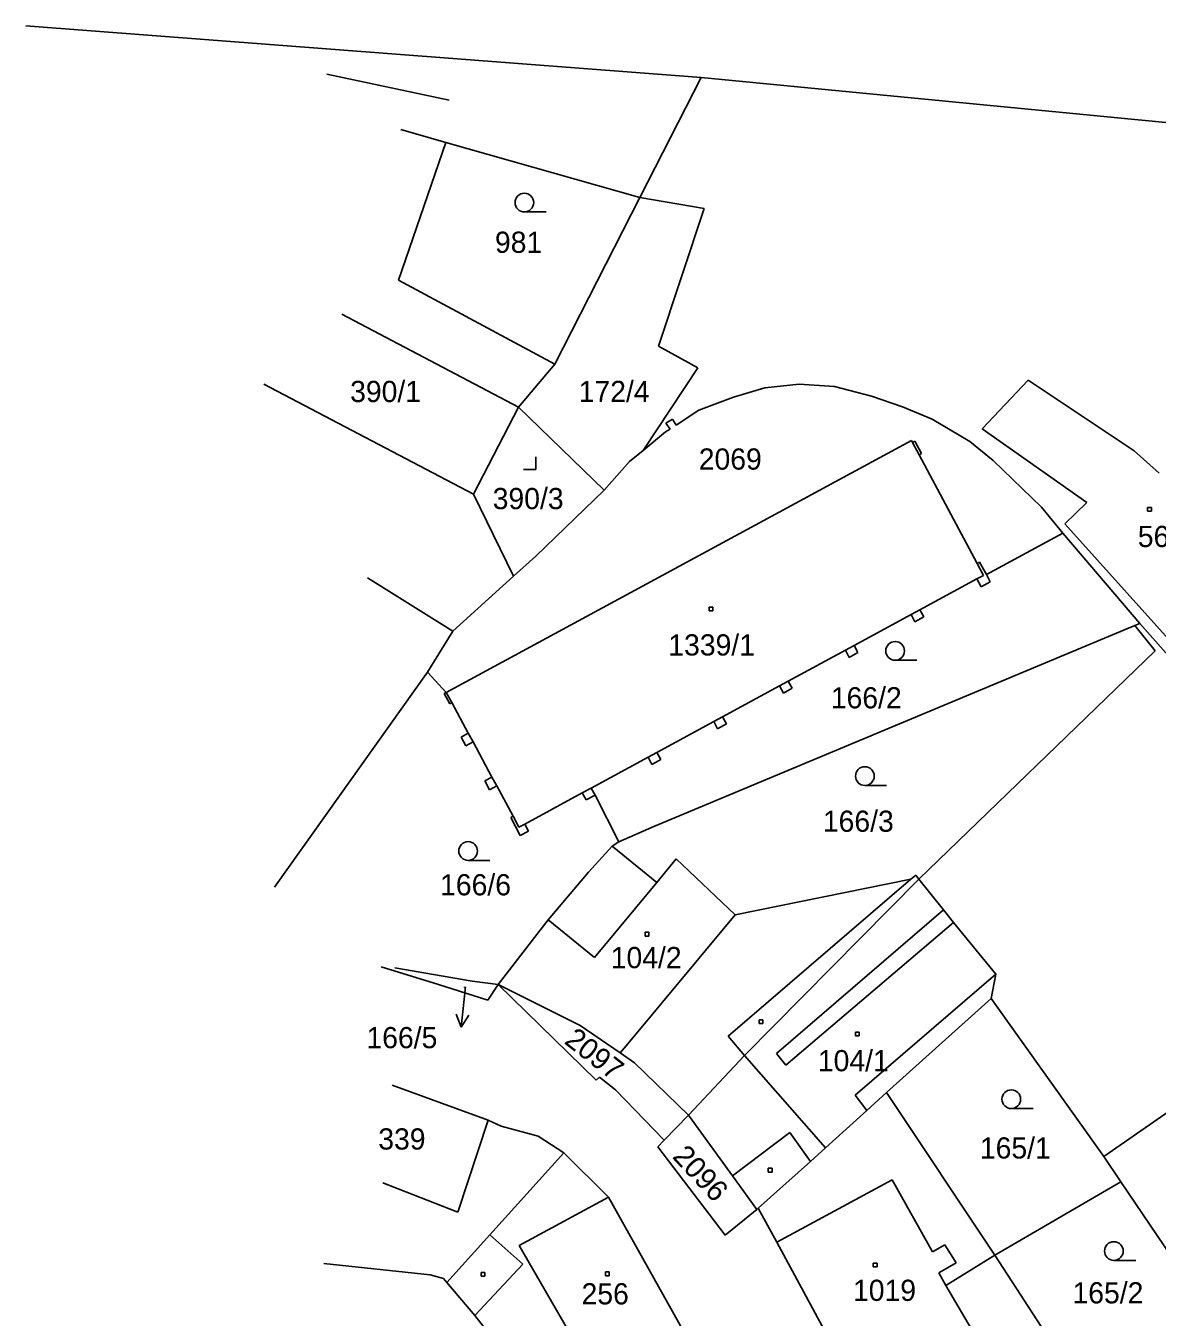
# Model space of a CAD drawing. Extents: x -711879 to -711361, y -1048782 to -1048177.
# Drawn here: x -711836.6 to -711745.8, y -1048542.7 to -1048439.1 of the extents above; entities that cross this region are included whole.
import ezdxf

# ---------------------------------------------------------------- set-up
doc = ezdxf.new("R2010")
doc.units = 0
for name, color, linetype in [('Vrstva 1', 7, 'Continuous'), ('Vrstva 10', 7, 'Continuous'), ('Vrstva 13', 7, 'Continuous'), ('Vrstva 14', 7, 'Continuous'), ('Vrstva 15', 7, 'Continuous'), ('Vrstva 16', 7, 'Continuous'), ('Vrstva 2', 7, 'Continuous'), ('Vrstva 23', 7, 'Continuous'), ('Vrstva 25', 7, 'Continuous'), ('Vrstva 46', 7, 'Continuous')]:
    doc.layers.add(name, color=color, linetype=linetype)

msp = doc.modelspace()

# ---------------------------------------------------------------- linework, layer by layer
at = {"layer": 'Vrstva 1'}
for p, q in [((-711782.37, -1048443.28), (-711836.55, -1048439.14)), ((-711782.37, -1048443.28), (-711787.28, -1048452.9)), ((-711782.37, -1048443.28), (-711733.69, -1048448.01)), ((-711802.84, -1048448.49), (-711806.47, -1048447.46)), ((-711806.66, -1048459.55), (-711802.84, -1048448.49)), ((-711787.28, -1048452.9), (-711802.84, -1048448.49)), ((-711794.1, -1048466.27), (-711787.28, -1048452.9)), ((-711787.28, -1048452.9), (-711782.12, -1048453.79)), ((-711782.12, -1048453.79), (-711785.8, -1048464.84)), ((-711794.1, -1048466.27), (-711806.66, -1048459.55)), ((-711785.8, -1048464.84), (-711782.62, -1048466.58)), ((-711797.01, -1048469.72), (-711794.1, -1048466.27)), ((-711782.62, -1048466.58), (-711787.03, -1048473.2)), ((-711759.82, -1048471.48), (-711756.13, -1048467.57)), ((-711756.13, -1048467.57), (-711747.61, -1048473.24)), ((-711800.63, -1048476.72), (-711817.46, -1048467.89)), ((-711779.78, -1048468.92), (-711777.25, -1048468.17)), ((-711777.25, -1048468.17), (-711774.5, -1048467.88)), ((-711774.5, -1048467.88), (-711771.66, -1048468.06)), ((-711771.66, -1048468.06), (-711768.7, -1048468.84)), ((-711797.01, -1048469.72), (-711800.63, -1048476.72)), ((-711790.15, -1048476.4), (-711797.01, -1048469.72)), ((-711782.56, -1048469.97), (-711779.78, -1048468.92)), ((-711768.7, -1048468.84), (-711766.22, -1048469.71)), ((-711766.22, -1048469.71), (-711763.83, -1048470.7)), ((-711785.21, -1048471), (-711784.67, -1048470.7)), ((-711784.67, -1048470.7), (-711784.36, -1048471.17)), ((-711784.36, -1048471.17), (-711782.56, -1048469.97)), ((-711763.83, -1048470.7), (-711760.8, -1048472.47)), ((-711787.03, -1048473.2), (-711785.22, -1048471.7)), ((-711785.22, -1048471.7), (-711784.85, -1048471.49)), ((-711784.85, -1048471.49), (-711785.21, -1048471)), ((-711751.43, -1048477.38), (-711759.82, -1048471.48)), ((-711802.81, -1048492.61), (-711765.5, -1048472.41)), ((-711765.5, -1048472.41), (-711765.41, -1048472.56)), ((-711765.41, -1048472.56), (-711765.21, -1048472.46)), ((-711765.21, -1048472.46), (-711764.68, -1048473.45)), ((-711760.8, -1048472.47), (-711758.94, -1048474)), ((-711787.03, -1048473.2), (-711788.11, -1048474.09)), ((-711764.68, -1048473.45), (-711764.88, -1048473.55)), ((-711764.88, -1048473.55), (-711760.22, -1048482.28)), ((-711747.61, -1048473.24), (-711745.62, -1048475.02)), ((-711788.11, -1048474.09), (-711790.15, -1048476.4)), ((-711758.94, -1048474), (-711755.05, -1048477.76)), ((-711800.63, -1048476.72), (-711797.41, -1048483.28)), ((-711790.15, -1048476.4), (-711795.64, -1048481.67)), ((-711755.05, -1048477.76), (-711754.44, -1048478.49)), ((-711753.19, -1048479.09), (-711751.43, -1048477.38)), ((-711754.44, -1048478.49), (-711753.35, -1048479.84)), ((-711759.48, -1048483.16), (-711753.35, -1048479.84)), ((-711753.35, -1048479.84), (-711747.16, -1048487.08)), ((-711742.97, -1048490.46), (-711753.19, -1048479.09)), ((-711795.64, -1048481.67), (-711797.41, -1048483.28)), ((-711760.22, -1048482.28), (-711760.03, -1048482.17)), ((-711760.03, -1048482.17), (-711759.48, -1048483.16)), ((-711759.48, -1048483.16), (-711759.17, -1048483.73)), ((-711802.28, -1048487.71), (-711809.14, -1048483.42)), ((-711797.41, -1048483.28), (-711802.28, -1048487.71)), ((-711760.24, -1048483.51), (-711764.81, -1048485.99)), ((-711759.9, -1048484.13), (-711760.24, -1048483.51)), ((-711759.17, -1048483.73), (-711759.9, -1048484.13)), ((-711764.81, -1048485.99), (-711764.5, -1048486.56)), ((-711747.56, -1048487.25), (-711786.15, -1048503.36)), ((-711765.52, -1048486.37), (-711770.09, -1048488.85)), ((-711765.21, -1048486.94), (-711765.52, -1048486.37)), ((-711764.5, -1048486.56), (-711765.21, -1048486.94)), ((-711747.16, -1048487.08), (-711747.56, -1048487.25)), ((-711745.93, -1048489.27), (-711747.56, -1048487.25)), ((-711747.16, -1048487.08), (-711735.52, -1048500.3)), ((-711804.33, -1048490.99), (-711802.28, -1048487.71)), ((-711770.79, -1048489.23), (-711775.37, -1048491.71)), ((-711770.48, -1048489.8), (-711770.79, -1048489.23)), ((-711769.78, -1048489.42), (-711770.48, -1048489.8)), ((-711770.09, -1048488.85), (-711769.78, -1048489.42)), ((-711764.91, -1048507.59), (-711745.93, -1048489.27)), ((-711804.33, -1048490.99), (-711816.6, -1048508.22)), ((-711802.81, -1048492.61), (-711804.33, -1048490.99)), ((-711776.07, -1048492.09), (-711780.64, -1048494.56)), ((-711775.76, -1048492.66), (-711776.07, -1048492.09)), ((-711775.06, -1048492.28), (-711775.76, -1048492.66)), ((-711775.37, -1048491.71), (-711775.06, -1048492.28)), ((-711802.99, -1048492.71), (-711802.81, -1048492.61)), ((-711802.54, -1048493.53), (-711802.99, -1048492.71)), ((-711802.37, -1048493.43), (-711802.54, -1048493.53)), ((-711801.05, -1048495.88), (-711802.37, -1048493.43)), ((-711780.64, -1048494.56), (-711780.33, -1048495.14)), ((-711781.35, -1048494.95), (-711785.92, -1048497.42)), ((-711781.04, -1048495.52), (-711781.35, -1048494.95)), ((-711780.33, -1048495.14), (-711781.04, -1048495.52)), ((-711801.62, -1048496.19), (-711801.05, -1048495.88)), ((-711801.24, -1048496.89), (-711801.62, -1048496.19)), ((-711800.67, -1048496.58), (-711801.24, -1048496.89)), ((-711799.15, -1048499.4), (-711800.67, -1048496.58)), ((-711785.92, -1048497.42), (-711785.61, -1048497.99)), ((-711786.62, -1048497.8), (-711791.19, -1048500.28)), ((-711786.31, -1048498.38), (-711786.62, -1048497.8)), ((-711785.61, -1048497.99), (-711786.31, -1048498.38)), ((-711799.72, -1048499.71), (-711799.15, -1048499.4)), ((-711799.34, -1048500.42), (-711799.72, -1048499.71)), ((-711798.77, -1048500.11), (-711799.34, -1048500.42)), ((-711797.45, -1048502.54), (-711798.77, -1048500.11)), ((-711791.9, -1048500.66), (-711796.52, -1048503.17)), ((-711791.59, -1048501.23), (-711791.9, -1048500.66)), ((-711791.19, -1048500.28), (-711790.88, -1048500.85)), ((-711790.88, -1048500.85), (-711791.59, -1048501.23)), ((-711790.88, -1048500.85), (-711788.96, -1048504.6)), ((-711797.64, -1048502.65), (-711797.45, -1048502.54)), ((-711796.89, -1048504.09), (-711797.64, -1048502.65)), ((-711796.23, -1048503.74), (-711796.89, -1048504.09)), ((-711796.52, -1048503.17), (-711796.23, -1048503.74)), ((-711788.96, -1048504.6), (-711786.15, -1048503.36)), ((-711789.51, -1048504.95), (-711791.39, -1048507.04)), ((-711788.96, -1048504.6), (-711789.51, -1048504.95)), ((-711789.51, -1048504.95), (-711785.93, -1048507.86)), ((-711784.36, -1048505.96), (-711785.93, -1048507.86)), ((-711784.36, -1048505.96), (-711779.64, -1048510.46)), ((-711791.39, -1048507.04), (-711794.63, -1048510.84)), ((-711779.64, -1048510.46), (-711765.55, -1048507.59)), ((-711778.88, -1048521.74), (-711764.91, -1048507.59)), ((-711765.55, -1048507.59), (-711765.15, -1048507.28)), ((-711765.15, -1048507.28), (-711764.91, -1048507.59)), ((-711764.91, -1048507.59), (-711762.93, -1048510.06)), ((-711762.93, -1048510.06), (-711762.13, -1048511.06)), ((-711794.63, -1048510.84), (-711798.64, -1048516.04)), ((-711762.13, -1048511.06), (-711758.71, -1048515.21)), ((-711808.03, -1048514.63), (-711803.44, -1048516.04)), ((-711800.73, -1048515.78), (-711806.94, -1048514.69)), ((-711758.71, -1048515.21), (-711759.09, -1048517.17)), ((-711803.44, -1048516.04), (-711799.48, -1048517.29)), ((-711798.64, -1048516.04), (-711800.73, -1048515.78)), ((-711799.48, -1048517.29), (-711798.64, -1048516.04)), ((-711798.64, -1048516.04), (-711790.79, -1048523.72)), ((-711792.08, -1048519.33), (-711798.64, -1048516.04)), ((-711767.48, -1048524.71), (-711759.09, -1048517.17)), ((-711759.09, -1048517.17), (-711750.06, -1048529.83)), ((-711788.87, -1048521.52), (-711792.08, -1048519.33)), ((-711787.7, -1048522.32), (-711788.87, -1048521.52)), ((-711783.39, -1048526.53), (-711787.7, -1048522.32)), ((-711783.39, -1048526.53), (-711778.88, -1048521.74)), ((-711790.79, -1048523.72), (-711790.51, -1048523.48)), ((-711790.51, -1048523.48), (-711789.25, -1048524.49)), ((-711807.15, -1048524.12), (-711799.45, -1048526.93)), ((-711789.25, -1048524.49), (-711785.33, -1048528.52)), ((-711769.06, -1048526.14), (-711767.48, -1048524.71)), ((-711767.48, -1048524.71), (-711758.79, -1048537.74)), ((-711750.06, -1048529.83), (-711743.26, -1048525.11)), ((-711785.33, -1048528.52), (-711783.39, -1048526.53)), ((-711779.86, -1048531.4), (-711783.39, -1048526.53)), ((-711772.4, -1048529.15), (-711769.06, -1048526.14)), ((-711798.4, -1048527.4), (-711799.45, -1048526.93)), ((-711795.44, -1048528.21), (-711798.4, -1048527.4)), ((-711793.39, -1048529.54), (-711795.44, -1048528.21)), ((-711785.85, -1048529.05), (-711785.33, -1048528.52)), ((-711793.39, -1048529.54), (-711799.32, -1048536.12)), ((-711789.8, -1048533.1), (-711793.39, -1048529.54)), ((-711785.85, -1048529.05), (-711780.45, -1048536.15)), ((-711773.6, -1048530.23), (-711772.4, -1048529.15)), ((-711748.68, -1048531.86), (-711750.06, -1048529.83)), ((-711773.6, -1048530.23), (-711777.78, -1048533.99)), ((-711777.91, -1048534.1), (-711779.86, -1048531.4)), ((-711758.79, -1048537.74), (-711748.68, -1048531.86)), ((-711742.68, -1048540.77), (-711748.68, -1048531.86)), ((-711783.4, -1048544.52), (-711789.8, -1048533.1)), ((-711777.91, -1048534.1), (-711780.45, -1048536.15)), ((-711777.78, -1048533.99), (-711777.91, -1048534.1)), ((-711777.78, -1048533.99), (-711776.3, -1048536.72)), ((-711799.32, -1048536.12), (-711802.77, -1048539.95)), ((-711776.3, -1048536.72), (-711769.67, -1048548.94)), ((-711758.79, -1048537.74), (-711762.73, -1048540.18)), ((-711758.79, -1048537.74), (-711750.15, -1048551.06)), ((-711804.11, -1048539.33), (-711812.65, -1048538.42)), ((-711803.04, -1048539.62), (-711804.11, -1048539.33)), ((-711802.77, -1048539.95), (-711803.04, -1048539.62)), ((-711800.52, -1048542.59), (-711802.77, -1048539.95)), ((-711762.73, -1048540.18), (-711760.67, -1048543.7)), ((-711796.39, -1048547.82), (-711800.52, -1048542.59))]:
    msp.add_line(p, q, dxfattribs=at)
at = {"layer": 'Vrstva 10'}
msp.add_line((-711812.4, -1048443.03), (-711802.59, -1048445.09), dxfattribs=at)
at = {"layer": 'Vrstva 13'}
msp.add_line((-711801.29, -1048516.26), (-711801.31, -1048516.47), dxfattribs=at)
at = {"layer": 'Vrstva 16'}
for p, q in [((-711801.31, -1048516.47), (-711801.618, -1048519.454)), ((-711801.618, -1048519.454), (-711802.013, -1048518.407)), ((-711801.618, -1048519.454), (-711801.018, -1048518.51))]:
    msp.add_line(p, q, dxfattribs=at)
at = {"layer": 'Vrstva 2'}
for p, q in [((-711797.01, -1048469.72), (-711811.19, -1048462.26)), ((-711764.88, -1048473.55), (-711765.41, -1048472.56)), ((-711759.71, -1048483.23), (-711760.22, -1048482.28)), ((-711760.24, -1048483.51), (-711759.71, -1048483.23)), ((-711765.52, -1048486.37), (-711764.81, -1048485.99)), ((-711770.79, -1048489.23), (-711770.09, -1048488.85)), ((-711776.07, -1048492.09), (-711775.37, -1048491.71)), ((-711802.81, -1048492.61), (-711802.37, -1048493.43)), ((-711781.35, -1048494.95), (-711780.64, -1048494.56)), ((-711801.05, -1048495.88), (-711800.67, -1048496.58)), ((-711786.62, -1048497.8), (-711785.92, -1048497.42)), ((-711799.15, -1048499.4), (-711798.77, -1048500.11)), ((-711791.9, -1048500.66), (-711791.19, -1048500.28)), ((-711796.98, -1048503.42), (-711797.45, -1048502.54)), ((-711796.52, -1048503.17), (-711796.98, -1048503.42)), ((-711785.93, -1048507.86), (-711790.91, -1048513.87)), ((-711780.21, -1048520.18), (-711765.55, -1048507.59)), ((-711762.93, -1048510.06), (-711776.32, -1048521.57)), ((-711794.63, -1048510.84), (-711790.91, -1048513.87)), ((-711779.64, -1048510.46), (-711788.37, -1048520.95)), ((-711762.13, -1048511.06), (-711775.56, -1048522.51)), ((-711758.71, -1048515.21), (-711770.01, -1048524.93)), ((-711778.88, -1048521.74), (-711780.21, -1048520.18)), ((-711788.37, -1048520.95), (-711788.87, -1048521.52)), ((-711772.4, -1048529.15), (-711778.88, -1048521.74)), ((-711776.32, -1048521.57), (-711775.56, -1048522.51)), ((-711770.01, -1048524.93), (-711769.06, -1048526.14)), ((-711799.45, -1048526.93), (-711801.89, -1048534.31)), ((-711775.26, -1048527.91), (-711779.86, -1048531.4)), ((-711773.6, -1048530.23), (-711775.26, -1048527.91)), ((-711776.3, -1048536.72), (-711767.04, -1048531.7)), ((-711767.04, -1048531.7), (-711763.8, -1048537.49)), ((-711801.89, -1048534.31), (-711807.9, -1048531.96)), ((-711789.8, -1048533.1), (-711796.96, -1048536.97)), ((-711799.32, -1048536.12), (-711796.67, -1048538.46)), ((-711790.3, -1048548.52), (-711796.96, -1048536.97)), ((-711763.8, -1048537.49), (-711762.8, -1048536.91)), ((-711762.8, -1048536.91), (-711761.91, -1048538.36)), ((-711796.67, -1048538.46), (-711800.52, -1048542.59)), ((-711761.91, -1048538.36), (-711763.3, -1048539.16)), ((-711763.3, -1048539.16), (-711762.73, -1048540.18))]:
    msp.add_line(p, q, dxfattribs=at)
at = {"layer": 'Vrstva 23'}
for p, q in [((-711796.55, -1048454.07), (-711794.8, -1048454.07)), ((-711795.62, -1048474.72), (-711795.62, -1048473.72)), ((-711795.62, -1048474.72), (-711796.62, -1048474.72)), ((-711766.8, -1048490.03), (-711765.05, -1048490.03)), ((-711769.23, -1048500.07), (-711767.48, -1048500.07)), ((-711801.06, -1048506.08), (-711799.31, -1048506.08)), ((-711757.48, -1048525.99), (-711755.73, -1048525.99)), ((-711749.25, -1048538.17), (-711747.5, -1048538.17))]:
    msp.add_line(p, q, dxfattribs=at)
for centre in [(-711796.55, -1048453.32), (-711766.8, -1048489.28), (-711769.23, -1048499.32), (-711801.06, -1048505.33), (-711757.48, -1048525.24), (-711749.25, -1048537.42)]:
    msp.add_circle(centre, 0.75, dxfattribs=at)
at = {"layer": 'Vrstva 25'}
for p, q in [((-711746.54, -1048477.78), (-711746.24, -1048477.78)), ((-711746.54, -1048478.08), (-711746.54, -1048477.78)), ((-711746.24, -1048477.78), (-711746.24, -1048478.08)), ((-711746.24, -1048478.08), (-711746.54, -1048478.08)), ((-711781.72, -1048485.76), (-711781.42, -1048485.76)), ((-711781.72, -1048486.06), (-711781.72, -1048485.76)), ((-711781.42, -1048486.06), (-711781.72, -1048486.06)), ((-711781.42, -1048485.76), (-711781.42, -1048486.06)), ((-711786.85, -1048511.85), (-711786.55, -1048511.85)), ((-711786.85, -1048512.15), (-711786.85, -1048511.85)), ((-711786.55, -1048512.15), (-711786.85, -1048512.15)), ((-711786.55, -1048511.85), (-711786.55, -1048512.15)), ((-711777.71, -1048518.88), (-711777.41, -1048518.88)), ((-711777.71, -1048519.18), (-711777.71, -1048518.88)), ((-711777.41, -1048519.18), (-711777.71, -1048519.18)), ((-711777.41, -1048518.88), (-711777.41, -1048519.18)), ((-711769.98, -1048519.86), (-711769.68, -1048519.86)), ((-711769.98, -1048520.16), (-711769.98, -1048519.86)), ((-711769.68, -1048520.16), (-711769.98, -1048520.16)), ((-711769.68, -1048519.86), (-711769.68, -1048520.16)), ((-711776.98, -1048530.78), (-711776.68, -1048530.78)), ((-711776.98, -1048531.08), (-711776.98, -1048530.78)), ((-711776.68, -1048530.78), (-711776.68, -1048531.08)), ((-711776.68, -1048531.08), (-711776.98, -1048531.08)), ((-711800.01, -1048539.13), (-711799.71, -1048539.13)), ((-711800.01, -1048539.43), (-711800.01, -1048539.13)), ((-711799.71, -1048539.13), (-711799.71, -1048539.43)), ((-711790.04, -1048539.1), (-711789.74, -1048539.1)), ((-711790.04, -1048539.4), (-711790.04, -1048539.1)), ((-711789.74, -1048539.1), (-711789.74, -1048539.4)), ((-711768.55, -1048538.4), (-711768.25, -1048538.4)), ((-711768.55, -1048538.7), (-711768.55, -1048538.4)), ((-711768.25, -1048538.7), (-711768.55, -1048538.7)), ((-711768.25, -1048538.4), (-711768.25, -1048538.7)), ((-711799.71, -1048539.43), (-711800.01, -1048539.43)), ((-711789.74, -1048539.4), (-711790.04, -1048539.4))]:
    msp.add_line(p, q, dxfattribs=at)
at = {"layer": 'Vrstva 46'}
for p, q in [((-711782.37, -1048443.28), (-711782.37, -1048443.28)), ((-711787.28, -1048452.9), (-711787.28, -1048452.9)), ((-711794.1, -1048466.27), (-711794.1, -1048466.27)), ((-711777.25, -1048468.17), (-711777.25, -1048468.17)), ((-711774.5, -1048467.88), (-711774.5, -1048467.88)), ((-711771.66, -1048468.06), (-711771.66, -1048468.06)), ((-711797.01, -1048469.72), (-711797.01, -1048469.72)), ((-711779.78, -1048468.92), (-711779.78, -1048468.92)), ((-711768.7, -1048468.84), (-711768.7, -1048468.84)), ((-711766.22, -1048469.71), (-711766.22, -1048469.71)), ((-711784.67, -1048470.7), (-711784.67, -1048470.7)), ((-711782.56, -1048469.97), (-711782.56, -1048469.97)), ((-711763.83, -1048470.7), (-711763.83, -1048470.7)), ((-711785.22, -1048471.7), (-711785.22, -1048471.7)), ((-711785.21, -1048471), (-711785.21, -1048471)), ((-711784.85, -1048471.49), (-711784.85, -1048471.49)), ((-711760.8, -1048472.47), (-711760.8, -1048472.47)), ((-711787.03, -1048473.2), (-711787.03, -1048473.2)), ((-711788.11, -1048474.09), (-711788.11, -1048474.09)), ((-711758.94, -1048474), (-711758.94, -1048474)), ((-711800.63, -1048476.72), (-711800.63, -1048476.72)), ((-711790.15, -1048476.4), (-711790.15, -1048476.4)), ((-711755.05, -1048477.76), (-711755.05, -1048477.76)), ((-711754.44, -1048478.49), (-711754.44, -1048478.49)), ((-711795.64, -1048481.67), (-711795.64, -1048481.67)), ((-711802.28, -1048487.71), (-711802.28, -1048487.71)), ((-711804.33, -1048490.99), (-711804.33, -1048490.99)), ((-711786.15, -1048503.36), (-711786.15, -1048503.36)), ((-711788.96, -1048504.6), (-711788.96, -1048504.6)), ((-711784.36, -1048505.96), (-711784.36, -1048505.96)), ((-711791.39, -1048507.04), (-711791.39, -1048507.04)), ((-711794.63, -1048510.84), (-711794.63, -1048510.84)), ((-711779.64, -1048510.46), (-711779.64, -1048510.46)), ((-711798.64, -1048516.04), (-711798.64, -1048516.04)), ((-711759.09, -1048517.17), (-711759.09, -1048517.17)), ((-711788.37, -1048520.95), (-711788.37, -1048520.95)), ((-711789.25, -1048524.49), (-711789.25, -1048524.49)), ((-711783.39, -1048526.53), (-711783.39, -1048526.53)), ((-711775.26, -1048527.91), (-711775.26, -1048527.91)), ((-711750.06, -1048529.83), (-711750.06, -1048529.83)), ((-711773.6, -1048530.23), (-711773.6, -1048530.23)), ((-711777.91, -1048534.1), (-711777.91, -1048534.1))]:
    msp.add_line(p, q, dxfattribs=at)

# ---------------------------------------------------------------- texts
at = {"layer": 'Vrstva 14'}
for s, height, p in [('981', 1.7, (-711798.91, -1048457.35)), ('172/4', 1.7, (-711792.19, -1048469.32)), ('2069', 1.7, (-711782.556, -1048474.74)), ('166/2', 1.7, (-711771.96, -1048493.89)), ('166/3', 1.7, (-711772.6, -1048503.79)), ('166/6', 1.7, (-711803.31, -1048508.89)), ('166/5', 0.1, (-711801.484, -1048516.26)), ('165/1', 1.7, (-711760, -1048530)), ('165/2', 1.7, (-711752.57, -1048541.62))]:
    msp.add_text(s, height=height, dxfattribs=at).set_placement(p)
for s, rotation, p in [('2097', 322.09254, (-711793.429, -1048520.715)), ('2096', 313.04997, (-711784.744, -1048529.902))]:
    msp.add_text(s, height=1.7, rotation=rotation, dxfattribs=at).set_placement(p)
at = {"layer": 'Vrstva 15'}
for s, p in [('390/1', (-711810.53, -1048469.32)), ('390/3', (-711799.09, -1048477.91)), ('561', (-711747.33, -1048480.95)), ('1339/1', (-711785, -1048489.65)), ('104/2', (-711789.62, -1048514.73)), ('104/1', (-711773, -1048523)), ('339', (-711808.27, -1048529.28)), ('256', (-711791.96, -1048541.7)), ('1019', (-711770.18, -1048541.42))]:
    msp.add_text(s, height=1.7, dxfattribs=at).set_placement(p)
at = {"layer": 'Vrstva 16'}
msp.add_text('166/5', height=1.7, dxfattribs=at).set_placement((-711809.22, -1048521.15))

doc.saveas('drawing.dxf')
